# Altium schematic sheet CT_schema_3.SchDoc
size 297 x 247 mm
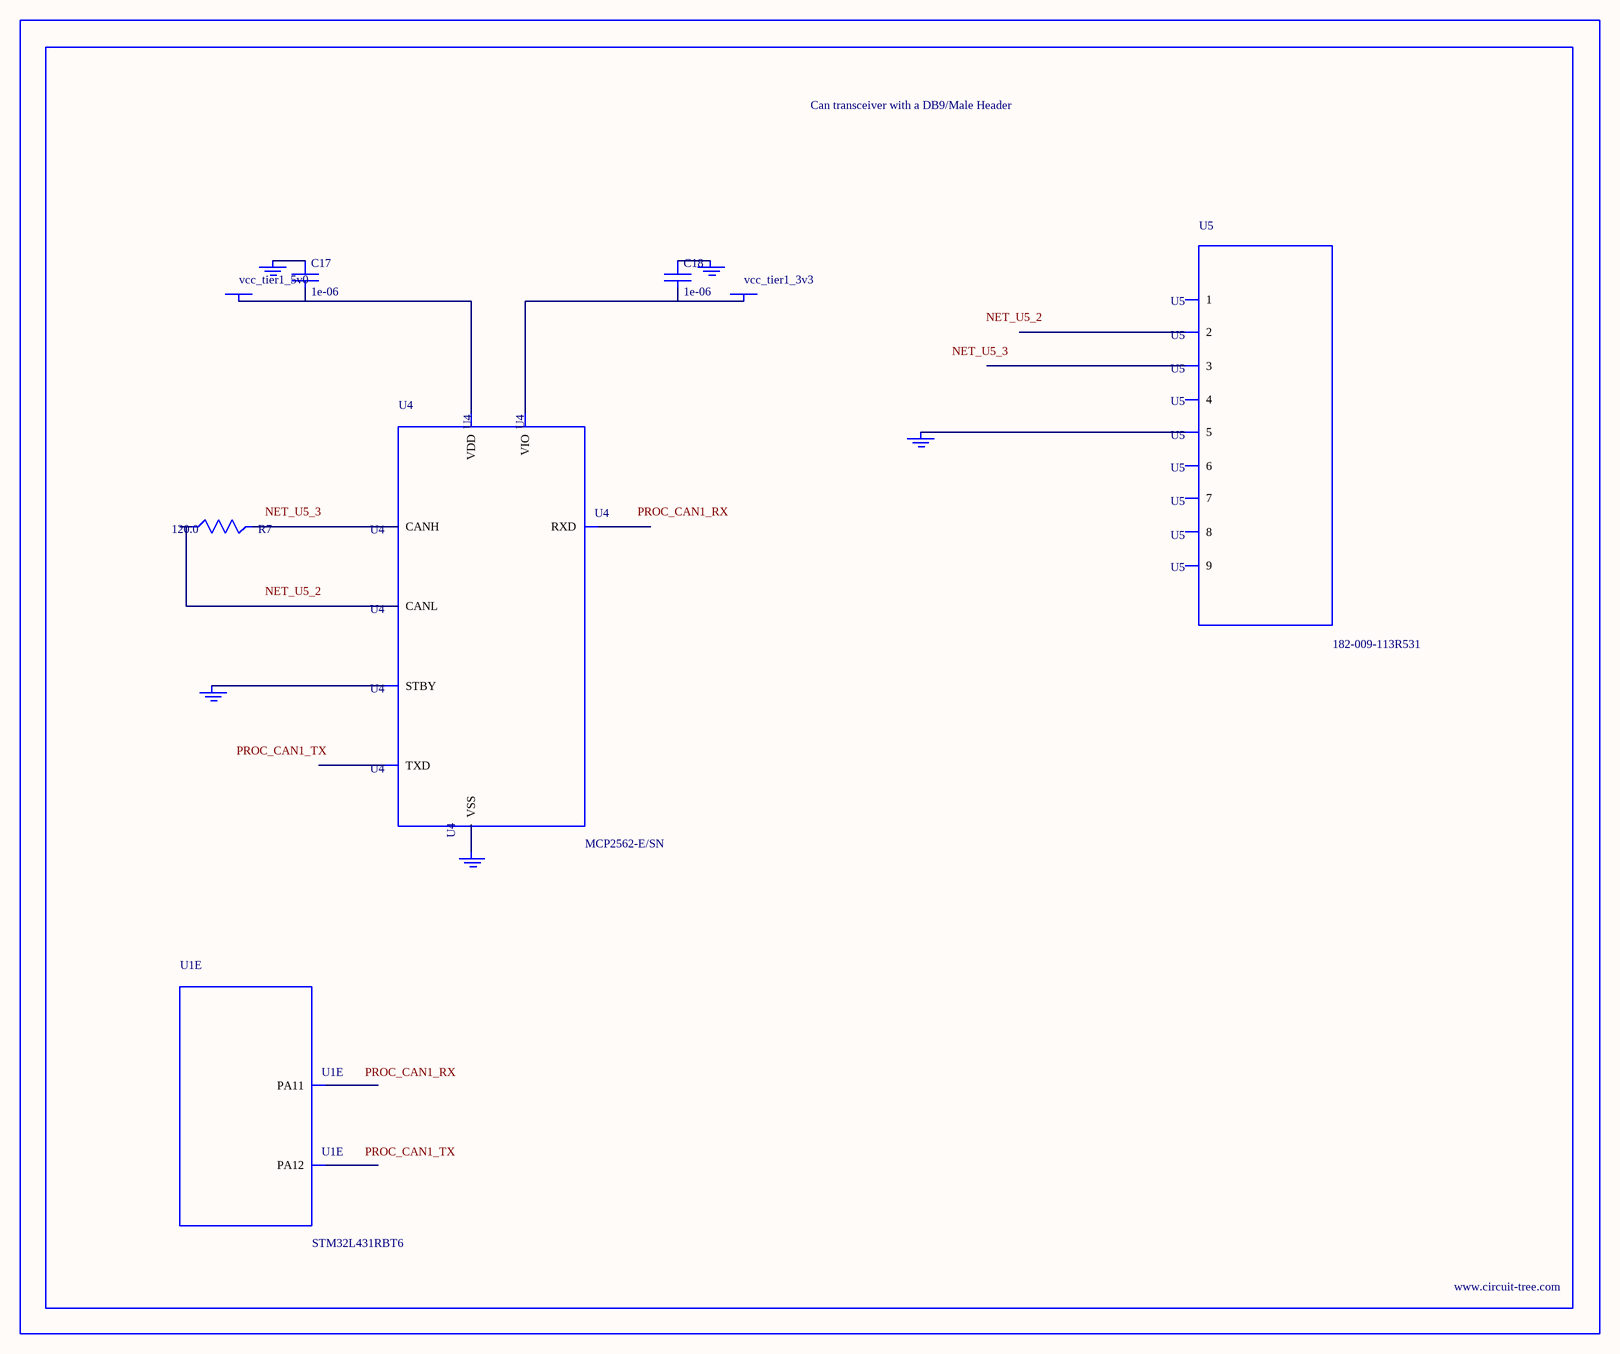
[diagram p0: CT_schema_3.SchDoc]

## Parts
BORDER2  (no value)
C17  1e-06  [C0603]
C18  1e-06  [C0603]
GND_INSTANCE_2_0  (no value)
GND_INSTANCE_2_1  (no value)
GND_INSTANCE_2_2  (no value)
GND_INSTANCE_2_3  (no value)
GND_INSTANCE_2_4  (no value)
POWER_INSTANCE_2_0  vcc_tier1_5v0
POWER_INSTANCE_2_1  vcc_tier1_3v3
R7  120.0  [R0603]
U1  STM32L431RBT6  [LQFP64]  (part E of 7)
U4  MCP2562-E/SN  [SOIC-8]
U5  182-009-113R531  [182-009-MALE]

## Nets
NetC17_1: C17.1 GND_INSTANCE_2_0.0(GND)
NetC17_2: C17.2 POWER_INSTANCE_2_0.0(PWR) U4.3(VDD)
NetC18_1: C18.1 GND_INSTANCE_2_1.0(GND)
NetC18_2: C18.2 POWER_INSTANCE_2_1.0(PWR) U4.5(VIO)
NetGND_INSTANCE_2_2_0: GND_INSTANCE_2_2.0(GND) U4.8(STBY)
NetGND_INSTANCE_2_3_0: GND_INSTANCE_2_3.0(GND) U4.2(VSS)
NetGND_INSTANCE_2_4_0: GND_INSTANCE_2_4.0(GND) U5.5
NetR7_1: R7.1 U4.6(CANL)
NetR7_2: R7.2 U4.7(CANH)

Not connected (* = marked no-connect by the designer): U1 44(PA11) 45(PA12); U4 1(TXD) 4(RXD); U5 1 2 3 4 6 7 8 9

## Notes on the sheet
- Labels drawn without touching a wire or pin: NET_U5_2, NET_U5_3, PROC_CAN1_RX, PROC_CAN1_TX

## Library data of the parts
BORDER2 = BORDER_PAGE2
C17 C18 = C0603C105K3RACTU
GND_INSTANCE_2_0-GND_INSTANCE_2_4 = GND
POWER_INSTANCE_2_0 POWER_INSTANCE_2_1 = PWR
R7 = RC0603JR-07120RL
